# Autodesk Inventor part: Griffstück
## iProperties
Created: 2006-12
Part Number: Griffstück
Document SubType Name: Modeling
Designer: Kumpf
Manufacturer: Standard
Standards Organization: Custom
Author: Kumpf
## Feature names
1. Drehung1 [Revolution]
2. Fase1 [Chamfer]
3. Fase2 [Chamfer]
4. Fase3 [Chamfer]
5. Fase4 [Chamfer]
6. Fase5 [Chamfer]
7. Fase6 [Chamfer]
8. Bohrung1 [Hole]
9. Bohrung2 [Hole]
